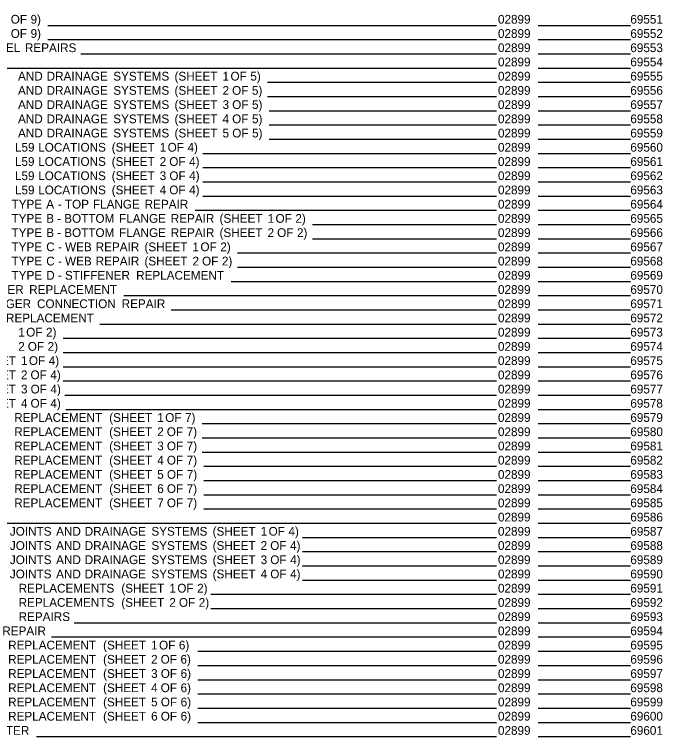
# Model space of a CAD drawing. Extents: x 76 to 3247, y 35 to 1167.
# Drawn here: x 381.2 to 825.2, y 87.2 to 582.2 of the extents above; entities that cross this region are included whole.
import ezdxf

# ---------------------------------------------------------------- set-up
doc = ezdxf.new("R2010")
doc.units = 0
doc.layers.add('Default', color=7, linetype='Continuous')

msp = doc.modelspace()

# ---------------------------------------------------------------- linework, layer by layer
at = {"layer": 'Default'}
for p, q in [((403.97, 574.65), (711.45, 574.65)), ((739.88, 574.65), (803.19, 574.65)), ((403.97, 564.9), (711.45, 564.9)), ((739.88, 564.9), (803.19, 564.9)), ((426.55, 555.15), (711.45, 555.15)), ((739.88, 555.15), (803.19, 555.15)), ((342.31, 545.4), (711.45, 545.4)), ((739.88, 545.4), (803.19, 545.4)), ((554.53, 535.65), (711.45, 535.65)), ((739.88, 535.65), (803.19, 535.65)), ((554.53, 525.9), (711.45, 525.9)), ((739.88, 525.9), (803.19, 525.9)), ((555.63, 516.15), (711.45, 516.15)), ((739.88, 516.15), (803.19, 516.15)), ((555.69, 506.4), (711.45, 506.4)), ((739.88, 506.4), (803.19, 506.4)), ((555.67, 496.65), (711.45, 496.65)), ((739.88, 496.65), (803.19, 496.65)), ((510.31, 486.9), (711.45, 486.9)), ((739.88, 486.9), (803.19, 486.9)), ((510.31, 477.15), (711.45, 477.15)), ((739.88, 477.15), (803.19, 477.15)), ((510.31, 467.4), (711.45, 467.4)), ((739.88, 467.4), (803.19, 467.4)), ((510.31, 457.65), (711.45, 457.65)), ((739.88, 457.65), (803.19, 457.65)), ((504.89, 447.9), (711.45, 447.9)), ((739.88, 447.9), (803.19, 447.9)), ((585.38, 438.15), (711.45, 438.15)), ((739.88, 438.15), (803.19, 438.15)), ((585.38, 428.4), (711.45, 428.4)), ((739.88, 428.4), (803.19, 428.4)), ((533.95, 418.65), (711.45, 418.65)), ((739.88, 418.65), (803.19, 418.65)), ((533.95, 408.9), (711.45, 408.9)), ((739.88, 408.9), (803.19, 408.9)), ((529.52, 399.15), (711.45, 399.15)), ((739.88, 399.15), (803.19, 399.15)), ((455.99, 389.4), (711.45, 389.4)), ((739.88, 389.4), (803.19, 389.4)), ((488.59, 379.65), (711.45, 379.65)), ((739.88, 379.65), (803.19, 379.65)), ((439.58, 369.9), (711.45, 369.9)), ((739.88, 369.9), (803.19, 369.9)), ((414.57, 360.15), (711.45, 360.15)), ((739.88, 360.15), (803.19, 360.15)), ((414.57, 350.4), (711.45, 350.4)), ((739.88, 350.4), (803.19, 350.4)), ((414.57, 340.65), (711.45, 340.65)), ((739.88, 340.65), (803.19, 340.65)), ((414.57, 330.9), (711.45, 330.9)), ((739.88, 330.9), (803.19, 330.9)), ((415.66, 321.15), (711.45, 321.15)), ((739.88, 321.15), (803.19, 321.15)), ((416.42, 311.4), (711.45, 311.4)), ((739.88, 311.4), (803.19, 311.4)), ((509.79, 301.65), (711.45, 301.65)), ((739.88, 301.65), (803.19, 301.65)), ((509.79, 291.9), (711.45, 291.9)), ((739.88, 291.9), (803.19, 291.9)), ((509.79, 282.15), (711.45, 282.15)), ((739.88, 282.15), (803.19, 282.15)), ((510.89, 272.4), (711.45, 272.4)), ((739.88, 272.4), (803.19, 272.4)), ((510.95, 262.65), (711.45, 262.65)), ((739.88, 262.65), (803.19, 262.65)), ((510.92, 252.9), (711.45, 252.9)), ((739.88, 252.9), (803.19, 252.9)), ((511, 243.15), (711.45, 243.15)), ((739.88, 243.15), (803.19, 243.15)), ((367.88, 233.4), (711.45, 233.4)), ((739.88, 233.4), (803.19, 233.4)), ((578.54, 223.65), (711.45, 223.65)), ((739.88, 223.65), (803.19, 223.65)), ((578.54, 213.9), (711.45, 213.9)), ((739.88, 213.9), (803.19, 213.9)), ((578.54, 204.15), (711.45, 204.15)), ((739.88, 204.15), (803.19, 204.15)), ((578.54, 194.4), (711.45, 194.4)), ((739.88, 194.4), (803.19, 194.4)), ((515.75, 184.65), (711.45, 184.65)), ((739.88, 184.65), (803.19, 184.65)), ((515.75, 174.9), (711.45, 174.9)), ((739.88, 174.9), (803.19, 174.9)), ((422.07, 165.15), (711.45, 165.15)), ((739.88, 165.15), (803.19, 165.15)), ((406.55, 155.4), (711.45, 155.4)), ((739.88, 155.4), (803.19, 155.4)), ((506.69, 145.65), (711.45, 145.65)), ((739.88, 145.65), (803.19, 145.65)), ((506.69, 135.9), (711.45, 135.9)), ((739.88, 135.9), (803.19, 135.9)), ((506.75, 126.15), (711.45, 126.15)), ((739.88, 126.15), (803.19, 126.15)), ((506.72, 116.4), (711.45, 116.4)), ((739.88, 116.4), (803.19, 116.4)), ((506.72, 106.65), (711.45, 106.65)), ((739.88, 106.65), (803.19, 106.65)), ((506.72, 96.9), (711.45, 96.9)), ((739.88, 96.9), (803.19, 96.9)), ((396.23, 87.15), (711.45, 87.15)), ((739.88, 87.15), (803.19, 87.15))]:
    msp.add_line(p, q, dxfattribs=at)

# ---------------------------------------------------------------- texts
for s, p in [(' OF', (376.38, 575.85)), (' 9)', (389.97, 575.85)), ('02899', (712.42, 575.85)), ('69551', (803.1, 575.85)), (' OF', (376.38, 566.1)), (' 9)', (389.97, 566.1)), ('02899', (712.42, 566.1)), ('69552', (803.1, 566.1)), (' STEEL', (357.5, 556.35)), (' REPAIRS', (386.1, 556.35)), ('02899', (712.42, 556.35)), ('69553', (803.1, 556.35)), ('02899', (712.42, 546.6)), ('69554', (803.1, 546.6)), (' AND', (381.38, 536.85)), (' DRAINAGE', (400.96, 536.85)), (' SYSTEMS', (446.63, 536.85)), (' (SHEET', (488.59, 536.85)), (' 1', (521.49, 536.85)), (' OF', (526.94, 536.85)), (' 5)', (540.53, 536.85)), ('02899', (712.42, 536.85)), ('69555', (803.1, 536.85)), (' AND', (381.38, 527.1)), (' DRAINAGE', (400.96, 527.1)), (' SYSTEMS', (446.63, 527.1)), (' (SHEET', (488.59, 527.1)), (' 2', (521.49, 527.1)), (' OF', (528.04, 527.1)), (' 5)', (541.62, 527.1)), ('02899', (712.42, 527.1)), ('69556', (803.1, 527.1)), (' AND', (381.38, 517.35)), (' DRAINAGE', (400.96, 517.35)), (' SYSTEMS', (446.63, 517.35)), (' (SHEET', (488.59, 517.35)), (' 3', (521.49, 517.35)), (' OF', (528.1, 517.35)), (' 5)', (541.69, 517.35)), ('02899', (712.42, 517.35)), ('69557', (803.1, 517.35)), (' AND', (381.38, 507.6)), (' DRAINAGE', (400.96, 507.6)), (' SYSTEMS', (446.63, 507.6)), (' (SHEET', (488.59, 507.6)), (' 4', (521.49, 507.6)), (' OF', (528.07, 507.6)), (' 5)', (541.66, 507.6)), ('02899', (712.42, 507.6)), ('69558', (803.1, 507.6)), (' AND', (381.38, 497.85)), (' DRAINAGE', (400.96, 497.85)), (' SYSTEMS', (446.63, 497.85)), (' (SHEET', (488.59, 497.85)), (' 5', (521.49, 497.85)), (' OF', (528.15, 497.85)), (' 5)', (541.73, 497.85)), ('02899', (712.42, 497.85)), ('69559', (803.1, 497.85)), (' L59', (379.27, 488.1)), (' LOCATIONS', (395.2, 488.1)), (' (SHEET', (445.54, 488.1)), (' 1', (478.45, 488.1)), (' OF', (483.89, 488.1)), (' 4)', (497.48, 488.1)), ('02899', (712.42, 488.1)), ('69560', (803.1, 488.1)), (' L59', (379.27, 478.35)), (' LOCATIONS', (395.2, 478.35)), (' (SHEET', (445.54, 478.35)), (' 2', (478.45, 478.35)), (' OF', (484.99, 478.35)), (' 4)', (498.58, 478.35)), ('02899', (712.42, 478.35)), ('69561', (803.1, 478.35)), (' L59', (379.27, 468.6)), (' LOCATIONS', (395.2, 468.6)), (' (SHEET', (445.54, 468.6)), (' 3', (478.45, 468.6)), (' OF', (485.05, 468.6)), (' 4)', (498.64, 468.6)), ('02899', (712.42, 468.6)), ('69562', (803.1, 468.6)), (' L59', (379.27, 458.85)), (' LOCATIONS', (395.2, 458.85)), (' (SHEET', (445.54, 458.85)), (' 4', (478.45, 458.85)), (' OF', (485.03, 458.85)), (' 4)', (498.61, 458.85)), ('02899', (712.42, 458.85)), ('69563', (803.1, 458.85)), (' TYPE', (376.92, 449.1)), (' A', (400.7, 449.1)), (' -', (408.63, 449.1)), (' TOP', (413.49, 449.1)), (' FLANGE', (432.69, 449.1)), (' REPAIR', (468.11, 449.1)), ('02899', (712.42, 449.1)), ('69564', (803.1, 449.1)), (' (SHEET', (519.44, 439.35)), (' 2)', (571.38, 439.35)), (' TYPE', (376.92, 439.35)), (' B', (400.7, 439.35)), (' -', (408.17, 439.35)), (' BOTTOM', (413.03, 439.35)), (' FLANGE', (450.59, 439.35)), (' REPAIR', (486.01, 439.35)), (' 1', (552.34, 439.35)), (' OF', (557.79, 439.35)), ('02899', (712.42, 439.35)), ('69565', (803.1, 439.35)), (' BOTTOM', (413.03, 429.6)), (' FLANGE', (450.59, 429.6)), (' (SHEET', (519.44, 429.6)), (' 2', (552.34, 429.6)), (' OF', (558.89, 429.6)), (' 2)', (572.47, 429.6)), ('02899', (712.42, 429.6)), ('69566', (803.1, 429.6)), (' TYPE', (376.92, 429.6)), (' B', (400.7, 429.6)), (' -', (408.17, 429.6)), (' REPAIR', (486.01, 429.6)), (' TYPE', (376.92, 419.85)), (' C', (400.7, 419.85)), (' WEB', (413.6, 419.85)), (' REPAIR', (434.58, 419.85)), (' (SHEET', (468.01, 419.85)), (' 1', (500.91, 419.85)), (' OF', (506.36, 419.85)), (' 2)', (519.95, 419.85)), ('02899', (712.42, 419.85)), ('69567', (803.1, 419.85)), (' -', (408.75, 419.85)), (' TYPE', (376.92, 410.1)), (' C', (400.7, 410.1)), (' WEB', (413.6, 410.1)), (' REPAIR', (434.58, 410.1)), (' (SHEET', (468.01, 410.1)), (' 2', (500.91, 410.1)), (' OF', (507.46, 410.1)), (' 2)', (521.04, 410.1)), ('02899', (712.42, 410.1)), ('69568', (803.1, 410.1)), (' -', (408.75, 410.1)), (' TYPE', (376.92, 400.35)), (' D', (400.7, 400.35)), (' STIFFENER', (413.49, 400.35)), (' REPLACEMENT', (462.28, 400.35)), ('02899', (712.42, 400.35)), ('69569', (803.1, 400.35)), (' -', (408.63, 400.35)), (' HANGER', (350.94, 390.6)), (' REPLACEMENT', (389.03, 390.6)), ('02899', (712.42, 390.6)), ('69570', (803.1, 390.6)), (' STRINGER', (348.84, 380.85)), (' CONNECTION', (394.38, 380.85)), (' REPAIR', (452.38, 380.85)), ('02899', (712.42, 380.85)), ('69571', (803.1, 380.85)), (' REPLACEMENT', (373.14, 371.1)), ('02899', (712.42, 371.1)), ('69572', (803.1, 371.1)), (' 1', (381.53, 361.35)), (' OF', (386.97, 361.35)), (' 2)', (400.56, 361.35)), ('02899', (712.42, 361.35)), ('69573', (803.1, 361.35)), (' 2', (381.53, 351.6)), (' OF', (388.07, 351.6)), (' 2)', (401.66, 351.6)), ('02899', (712.42, 351.6)), ('69574', (803.1, 351.6)), (' (SHEET', (350.47, 341.85)), (' 1', (383.38, 341.85)), (' OF', (388.83, 341.85)), (' 4)', (402.41, 341.85)), ('02899', (712.42, 341.85)), ('69575', (803.1, 341.85)), (' (SHEET', (350.47, 332.1)), (' 2', (383.38, 332.1)), (' OF', (389.92, 332.1)), (' 4)', (403.51, 332.1)), ('02899', (712.42, 332.1)), ('69576', (803.1, 332.1)), (' (SHEET', (350.47, 322.35)), (' 3', (383.38, 322.35)), (' OF', (389.99, 322.35)), (' 4)', (403.57, 322.35)), ('02899', (712.42, 322.35)), ('69577', (803.1, 322.35)), (' (SHEET', (350.47, 312.6)), (' 4', (383.38, 312.6)), (' OF', (389.96, 312.6)), (' 4)', (403.55, 312.6)), ('02899', (712.42, 312.6)), ('69578', (803.1, 312.6)), (' REPLACEMENT', (378.79, 302.85)), (' (SHEET', (443.85, 302.85)), (' 1', (476.75, 302.85)), (' OF', (482.2, 302.85)), (' 7)', (495.78, 302.85)), ('02899', (712.42, 302.85)), ('69579', (803.1, 302.85)), (' REPLACEMENT', (378.79, 293.1)), (' (SHEET', (443.85, 293.1)), (' 2', (476.75, 293.1)), (' OF', (483.29, 293.1)), (' 7)', (496.88, 293.1)), ('02899', (712.42, 293.1)), ('69580', (803.1, 293.1)), (' REPLACEMENT', (378.79, 283.35)), (' (SHEET', (443.85, 283.35)), (' 3', (476.75, 283.35)), (' OF', (483.36, 283.35)), (' 7)', (496.94, 283.35)), ('02899', (712.42, 283.35)), ('69581', (803.1, 283.35)), (' REPLACEMENT', (378.79, 273.6)), (' (SHEET', (443.85, 273.6)), (' 4', (476.75, 273.6)), (' OF', (483.33, 273.6)), (' 7)', (496.92, 273.6)), ('02899', (712.42, 273.6)), ('69582', (803.1, 273.6)), (' REPLACEMENT', (378.79, 263.85)), (' (SHEET', (443.85, 263.85)), (' 5', (476.75, 263.85)), (' OF', (483.4, 263.85)), (' 7)', (496.99, 263.85)), ('02899', (712.42, 263.85)), ('69583', (803.1, 263.85)), (' REPLACEMENT', (378.79, 254.1)), (' (SHEET', (443.85, 254.1)), (' 6', (476.75, 254.1)), (' OF', (483.36, 254.1)), (' 7)', (496.94, 254.1)), ('02899', (712.42, 254.1)), ('69584', (803.1, 254.1)), (' REPLACEMENT', (378.79, 244.35)), (' (SHEET', (443.85, 244.35)), (' 7', (476.75, 244.35)), (' OF', (483.36, 244.35)), (' 7)', (496.94, 244.35)), ('02899', (712.42, 244.35)), ('69585', (803.1, 244.35)), ('02899', (712.42, 234.6)), ('69586', (803.1, 234.6)), (' JOINTS', (375.79, 224.85)), (' AND', (407.49, 224.85)), (' DRAINAGE', (427.08, 224.85)), (' SYSTEMS', (472.75, 224.85)), (' (SHEET', (514.71, 224.85)), (' 1', (547.61, 224.85)), (' OF', (553.06, 224.85)), (' 4)', (566.64, 224.85)), ('02899', (712.42, 224.85)), ('69587', (803.1, 224.85)), (' JOINTS', (375.79, 215.1)), (' AND', (407.49, 215.1)), (' DRAINAGE', (427.08, 215.1)), (' SYSTEMS', (472.75, 215.1)), (' (SHEET', (514.71, 215.1)), (' 2', (547.61, 215.1)), (' OF', (554.15, 215.1)), (' 4)', (567.74, 215.1)), ('02899', (712.42, 215.1)), ('69588', (803.1, 215.1)), (' JOINTS', (375.79, 205.35)), (' AND', (407.49, 205.35)), (' DRAINAGE', (427.08, 205.35)), (' SYSTEMS', (472.75, 205.35)), (' (SHEET', (514.71, 205.35)), (' 3', (547.61, 205.35)), (' OF', (554.22, 205.35)), (' 4)', (567.81, 205.35)), ('02899', (712.42, 205.35)), ('69589', (803.1, 205.35)), (' JOINTS', (375.79, 195.6)), (' AND', (407.49, 195.6)), (' DRAINAGE', (427.08, 195.6)), (' SYSTEMS', (472.75, 195.6)), (' (SHEET', (514.71, 195.6)), (' 4', (547.61, 195.6)), (' OF', (554.19, 195.6)), (' 4)', (567.78, 195.6)), ('02899', (712.42, 195.6)), ('69590', (803.1, 195.6)), (' REPLACEMENTS', (381.78, 185.85)), (' (SHEET', (452.15, 185.85)), (' 1', (485.06, 185.85)), (' OF', (490.51, 185.85)), (' 2)', (504.09, 185.85)), ('02899', (712.42, 185.85)), ('69591', (803.1, 185.85)), (' REPLACEMENTS', (381.78, 176.1)), (' (SHEET', (452.15, 176.1)), (' 2', (485.06, 176.1)), (' OF', (491.6, 176.1)), (' 2)', (505.19, 176.1)), ('02899', (712.42, 176.1)), ('69592', (803.1, 176.1)), (' REPAIRS', (381.78, 166.35)), ('02899', (712.42, 166.35)), ('69593', (803.1, 166.35)), (' REPAIR', (370.61, 156.6)), ('02899', (712.42, 156.6)), ('69594', (803.1, 156.6)), (' REPLACEMENT', (374.59, 146.85)), (' (SHEET', (439.65, 146.85)), (' 1', (472.55, 146.85)), (' OF', (478, 146.85)), (' 6)', (491.58, 146.85)), ('02899', (712.42, 146.85)), ('69595', (803.1, 146.85)), (' REPLACEMENT', (374.59, 137.1)), (' (SHEET', (439.65, 137.1)), (' 2', (472.55, 137.1)), (' OF', (479.1, 137.1)), (' 6)', (492.68, 137.1)), ('02899', (712.42, 137.1)), ('69596', (803.1, 137.1)), (' (SHEET', (439.65, 127.35)), (' 6)', (492.75, 127.35)), (' REPLACEMENT', (374.59, 127.35)), (' 3', (472.55, 127.35)), (' OF', (479.16, 127.35)), ('02899', (712.42, 127.35)), ('69597', (803.1, 127.35)), (' (SHEET', (439.65, 117.6)), (' 6)', (492.72, 117.6)), (' REPLACEMENT', (374.59, 117.6)), (' 4', (472.55, 117.6)), (' OF', (479.13, 117.6)), ('02899', (712.42, 117.6)), ('69598', (803.1, 117.6)), (' REPLACEMENT', (374.59, 107.85)), (' (SHEET', (439.65, 107.85)), (' OF', (479.2, 107.85)), (' 6)', (492.79, 107.85)), ('02899', (712.42, 107.85)), ('69599', (803.1, 107.85)), (' 5', (472.55, 107.85)), (' REPLACEMENT', (374.59, 98.1)), (' (SHEET', (439.65, 98.1)), (' 6', (472.55, 98.1)), (' OF', (479.16, 98.1)), (' 6)', (492.75, 98.1)), ('02899', (712.42, 98.1)), ('69600', (803.1, 98.1)), (' GUTTER', (356.14, 88.35)), ('02899', (712.42, 88.35)), ('69601', (803.1, 88.35))]:
    msp.add_text(s, height=6, dxfattribs=at).set_placement(p)

doc.saveas('drawing.dxf')
